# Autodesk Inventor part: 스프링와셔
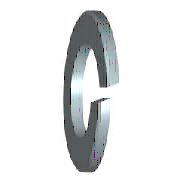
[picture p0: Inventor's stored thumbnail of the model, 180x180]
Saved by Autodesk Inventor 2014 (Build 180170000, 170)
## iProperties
IsCustomPart: 1
Created: 2012-02
Part Number: 스프링와셔
Material: 강철, 연강
Description: 스프링 와셔
Document SubType Name: Modeling
Standard: JIS B 1251
Designer: mduedu
Standards Organization: JIS
Language: ko-KR
Size Designation: 번호 2 4
Categories: <MemberInstance><Categories><Category DisplayName="조임쇠" InternalName="e4da775c-781d-43d5-af7c-5136215cf5a6" Mnemonic="FSTN"><Category DisplayName="와셔" InternalN
Density: 1 g/cm^3
Appearance: 파란색 - 벽 페인트 - 광택
Author: mduedu
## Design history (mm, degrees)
sketch "스케치1"
  geometry: C1 r 3.8 at (0, 0); C2 r 2.05 at (0, 0); 1 further point
  constraints: 2 centre point, 2 coincident
  dimensions: "d0" = 4.1 diameter of C2 (= SD1); "d1" = 7.6 diameter of C1 (= SD2)
extrude "본체" new body sketch "스케치1" distance "d2" = 1 (= SD); taper "d3" = 0 deg
sketch "스케치2"
  geometry: L1 (0, -2.05)-(0, 2.05) reference; L2 (1, 3.8)-(1, -3.8) reference; L3 (-1.2, 0)-(7.2, 0) reference; L4 (0, -0.2)-(1, 0.164); L5 (0, 0.2)-(1, 0.564)
  constraints: 4 end point, 4 point on line, 1 parallel
  dimensions: "d4" = 0.2 distance from line of L3 L4.start (= 0.2 x SD); "d5" = 0.2 distance from line of L3 L5.start (= 0.2 x SD); "d6" = 70 deg angle of L2 L4 (= FAWI)
extrude "절단부" cut sketch "스케치2" stored distance "d7" = 1 (= SD); taper "d8" = 0 deg
workaxis "Work Axis1"
workplane "Work Plane1"
body "Solid1"
other parameters: "SD1" = 4.1 [user parameter; used in 1 equation term], "SD2" = 7.6 [user parameter; used in 1 equation term], "SD" = 1 [user parameter; used in 4 equation terms], "FAWI" = 70 deg [user parameter; used in 1 equation term], "d9" = 0, "d10" = 0, "d11" = 0, "d12" = 0, "SDI" = 1.4 [user parameter], "NND" = 4 [user parameter]
